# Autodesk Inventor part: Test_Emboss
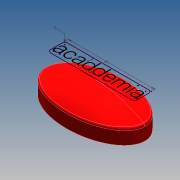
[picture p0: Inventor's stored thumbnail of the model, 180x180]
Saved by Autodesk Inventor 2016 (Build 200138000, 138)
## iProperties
Created: 2015-09
Part Number: Test_Emboss
Material: Generic
Document SubType Name: Modeling
Designer: julian.chica
Density: 1 g/cm^3
Appearance: Smooth - Red
Mass: 32.3221 g
Surface Area: 70.1364 cm^2
Volume: 32.3221 cm^3
Author: julian.chica
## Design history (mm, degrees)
sketch "Sketch2" dims "d0" = 35, "d1" = 20
  geometry: 2 further points; 1 other entity
  constraints: 1 coincident, 2 other
extrude "Extrusion1" new body sketch "Sketch2" distance "d2" = 10; taper "d3" = 0 deg
workplane "Work Plane1"
workpoint "Work Point1"
loft "Loft1" dims "d5" = 0, "d6" = 90 deg, "d7" = 10, "d8" = 90 deg
  node "Edges1"
fillet "Fillet1" dims "d9" = 2
workplane "Work Plane2"
sketch "ACADDEMIA"
  geometry: L1 (-32.972, 8.256)-(32.972, 8.256); L2 (32.972, 8.256)-(32.972, 0); L3 (32.972, 0)-(-32.972, 0); L4 (-32.972, 0)-(-32.972, 8.256); 2 further points
  constraints: 1 coincident, 1 midpoint, 2 other
sketch "BORDE"
  geometry: L1 (-28.5, 9)-(28.5, 9); L2 (30.5, 7)-(30.5, -1); L3 (28.5, -3)-(-28.5, -3); L4 (-30.5, -1)-(-30.5, 7); A1 r 2 centre (-28.5, 7) between (-28.5, 9) and (-30.5, 7); A2 r 2 centre (28.5, 7) between (30.5, 7) and (28.5, 9); A3 r 2 centre (28.5, -1) between (28.5, -3) and (30.5, -1); A4 r 2 centre (-28.5, -1) between (-30.5, -1) and (-28.5, -3); 4 further points
  constraints: 8 end point, 8 point on circle, 8 tangent, 4 centre point, 4 point on line, 3 equal radius, 2 parallel, 1 horizontal, 1 midpoint, 1 perpendicular, 1 vertical alignment
  dimensions: "d13" = 3 distance from line of L3 point (0, 0); "d14" = 9 distance from line of point (0, 0) L1; "d15" = 61 distance of point (-30.5, 9) point (30.5, 9); "d16" = 2 radius of A1
body "Solid1"
other parameters: "d10" = 3.5
